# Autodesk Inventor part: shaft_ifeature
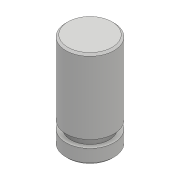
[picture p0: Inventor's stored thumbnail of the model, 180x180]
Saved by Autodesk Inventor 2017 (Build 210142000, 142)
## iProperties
Created: 2016-08
Part Number: shaft_ifeature
Material: Generic
Document SubType Name: Modeling
Designer: Sandeep
Density: 1 g/cm^3
Appearance: Default
Author: Sandeep
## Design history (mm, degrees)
sketch "Sketch1"
  geometry: C1 r 25 at (0, 0); 1 further point
  constraints: 1 centre point, 1 coincident
  dimensions: "d0" = 50 diameter of C1
extrude "Extrusion1" new body sketch "Sketch1" distance "d1" = 100; taper "d2" = 0 deg
chamfer "Chamfer1" distance "d3" = 2; stored, may be unused: second distance "d4" = 2, angle "d5" = 45 deg
chamfer "Chamfer2" distance "d6" = 2; stored, may be unused: second distance "d7" = 2, angle "d8" = 45 deg
sketch "Sketch3"
  geometry: L1 (-25, 23)-(-20, 23); L2 (-20, 23)-(-20, 15); L3 (-20, 15)-(-25, 15); L4 (-25, 15)-(-25, 23); L5 (0, 0)-(0, 35)
  constraints: 10 end point, 2 parallel, 1 horizontal, 1 perpendicular, 1 vertical
  dimensions: "d13" = 8 distance of L3.end L1.start; "d14" = 25 distance between parallel lines of L4 L5; "d15" = 20 distance between parallel lines of L2 L5; "d17" = 15 distance from line of L3 L5.start
revolve "Revolution2" sketch "Sketch3" stored, may be unused: angle "d18" = 90 deg
body "Solid1"
